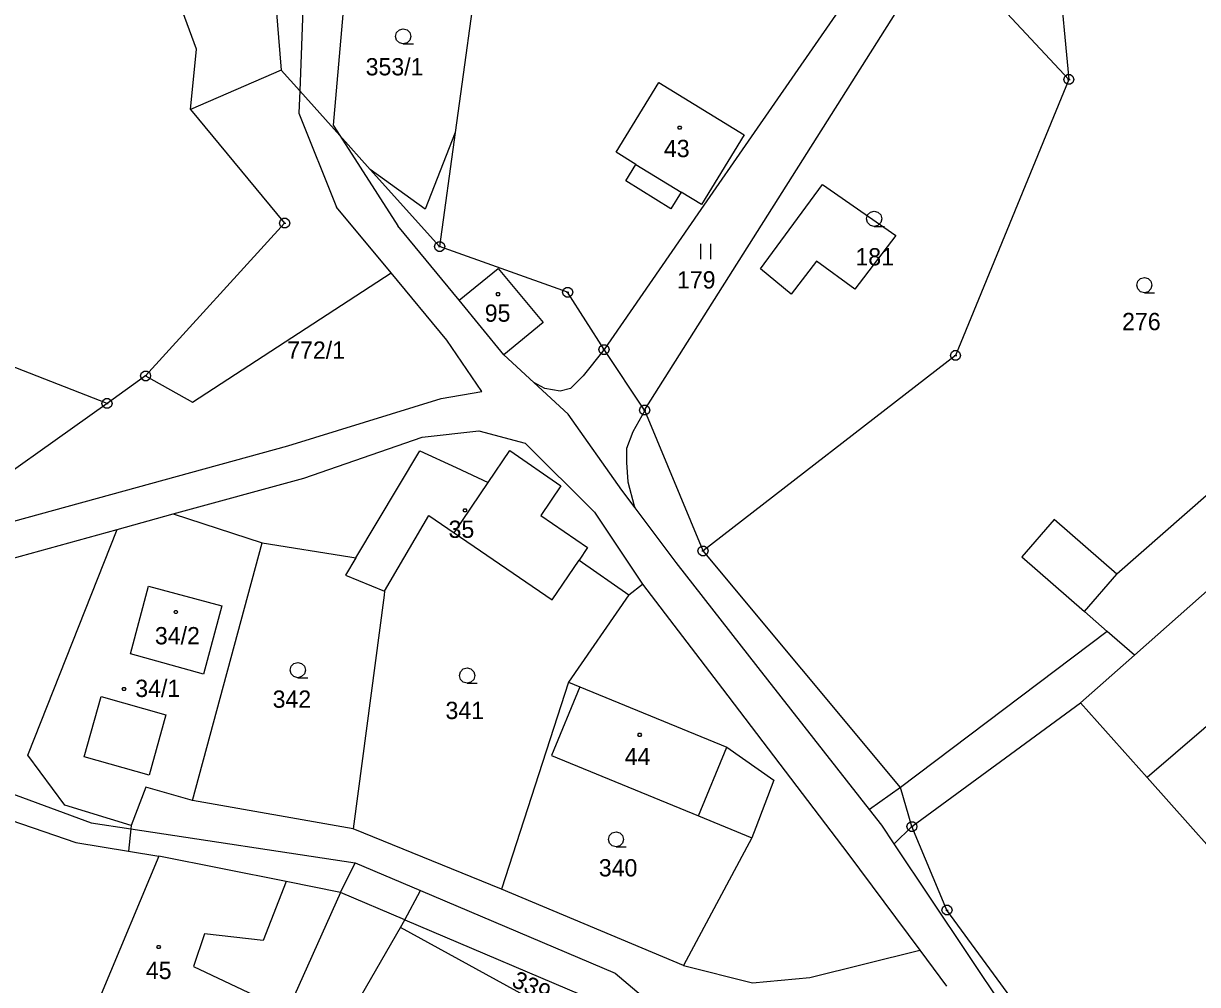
# Model space of a CAD drawing. Extents: x -694465 to -690527, y -983694 to -978978.
# Drawn here: x -693618.8 to -693503.4, y -981377.5 to -981283 of the extents above; entities that cross this region are included whole.
import ezdxf

# ---------------------------------------------------------------- set-up
doc = ezdxf.new("R2010")
doc.units = 0
for name, color, linetype in [('Vrstva 1', 7, 'Continuous'), ('Vrstva 18', 7, 'Continuous'), ('Vrstva 19', 7, 'Continuous'), ('Vrstva 24', 7, 'Continuous'), ('Vrstva 25', 7, 'Continuous')]:
    doc.layers.add(name, color=color, linetype=linetype)

msp = doc.modelspace()

# ---------------------------------------------------------------- linework, layer by layer
at = {"layer": 'Vrstva 1'}
for points in [[(-693518.05, -981266.92), (-693516.01, -981288.45)], [(-693594.85, -981270.62), (-693593.46, -981287.56)], [(-693531.56, -981271.43), (-693546.95, -981293.69)], [(-693601.8, -981285.49), (-693606.64, -981272.26)], [(-693590.99, -981271.78), (-693591.65, -981289.58)], [(-693586.58, -981272.65), (-693588.36, -981292.94)], [(-693557.73, -981320.98), (-693528.64, -981274.92)], [(-693516.01, -981288.45), (-693528.64, -981274.92)], [(-693573.91, -981275.82), (-693576.35, -981293.68)], [(-693602.38, -981291.42), (-693601.8, -981285.49)], [(-693593.46, -981287.56), (-693602.38, -981291.42)], [(-693591.65, -981289.58), (-693593.46, -981287.56)], [(-693558.58, -981296.82), (-693560.54, -981295.62), (-693556.34, -981288.75), (-693547.93, -981293.91)], [(-693516.01, -981288.45), (-693527.15, -981315.6)], [(-693591.65, -981289.58), (-693591.73, -981291.78)], [(-693587.69, -981293.98), (-693591.65, -981289.58)], [(-693602.38, -981291.42), (-693593.13, -981302.59)], [(-693591.73, -981291.78), (-693588.03, -981301.01)], [(-693588.36, -981292.94), (-693587.69, -981293.98)], [(-693584.71, -981297.3), (-693587.69, -981293.98)], [(-693587.69, -981293.98), (-693582.01, -981302.86)], [(-693576.35, -981293.68), (-693579.31, -981301.23)], [(-693576.35, -981293.68), (-693577.89, -981304.9)], [(-693547.93, -981293.91), (-693552.13, -981300.75), (-693554.14, -981299.53)], [(-693546.95, -981293.69), (-693552.48, -981301.67)], [(-693554.14, -981299.53), (-693555.14, -981301.17), (-693559.57, -981298.44), (-693558.58, -981296.82)], [(-693558.58, -981296.82), (-693554.14, -981299.53)], [(-693577.89, -981304.9), (-693584.71, -981297.3)], [(-693579.31, -981301.23), (-693584.71, -981297.3)], [(-693540.23, -981298.787), (-693533.033, -981303.821), (-693537.048, -981309.088), (-693540.812, -981306.329), (-693543.322, -981309.589), (-693546.333, -981307.082), (-693540.23, -981298.787)], [(-693582.661, -981307.477), (-693588.03, -981301.01)], [(-693593.13, -981302.59), (-693606.81, -981317.62)], [(-693552.48, -981301.67), (-693561.72, -981315.03)], [(-693575.97, -981310.18), (-693582.01, -981302.86)], [(-693565.3, -981309.39), (-693577.89, -981304.9)], [(-693575.97, -981310.18), (-693572.13, -981307.04)], [(-693572.13, -981307.04), (-693567.72, -981312.38), (-693571.58, -981315.54)], [(-693606.81, -981317.62), (-693602.192, -981320.191), (-693582.661, -981307.477)], [(-693577.17, -981314.09), (-693582.661, -981307.477)], [(-693610.6, -981320.32), (-693639.5, -981309.039)], [(-693561.72, -981315.03), (-693565.3, -981309.39)], [(-693571.58, -981315.54), (-693575.97, -981310.18)], [(-693573.75, -981319.16), (-693577.17, -981314.09)], [(-693561.72, -981315.03), (-693563.774, -981317.615), (-693565.028, -981318.869), (-693566.032, -981319.119), (-693567.538, -981318.869), (-693568.64, -981318.257)], [(-693557.73, -981320.98), (-693561.72, -981315.03)], [(-693486.54, -981315.4), (-693511.29, -981337.12)], [(-693568.64, -981318.257), (-693571.58, -981315.54)], [(-693527.15, -981315.6), (-693551.98, -981334.83)], [(-693606.81, -981317.62), (-693610.6, -981320.32)], [(-693565.25, -981321.39), (-693568.64, -981318.257)], [(-693592.81, -981324.5), (-693577.74, -981319.85)], [(-693577.74, -981319.85), (-693573.75, -981319.16)], [(-693610.6, -981320.32), (-693625.72, -981331.09)], [(-693557.71, -981321.027), (-693558.88, -981323.132), (-693559.508, -981324.762), (-693559.508, -981326.141), (-693559.382, -981328.022), (-693558.755, -981330.405), (-693558.663, -981330.589)], [(-693557.71, -981321.027), (-693557.73, -981320.98)], [(-693551.98, -981334.83), (-693557.71, -981321.027)], [(-693559.97, -981328.85), (-693565.25, -981321.39)], [(-693579.62, -981323.63), (-693574.03, -981323.01)], [(-693574.03, -981323.01), (-693569.46, -981324.23)], [(-693619.77, -981331.92), (-693592.81, -981324.5)], [(-693591.26, -981327.68), (-693579.62, -981323.63)], [(-693569.46, -981324.23), (-693562.66, -981331.03)], [(-693586.13, -981335.51), (-693579.85, -981324.99), (-693576.27, -981326.64), (-693573.1, -981328.1)], [(-693573.1, -981328.1), (-693570.97, -981324.97), (-693565.97, -981328.43), (-693567.95, -981331.34)], [(-693604.08, -981331.2), (-693591.26, -981327.68)], [(-693576.47, -981333.04), (-693573.1, -981328.1)], [(-693558.663, -981330.589), (-693559.97, -981328.85)], [(-693609.59, -981332.72), (-693604.08, -981331.2)], [(-693604.08, -981331.2), (-693595.35, -981334.04)], [(-693583.3, -981338.78), (-693578.95, -981331.35)], [(-693578.95, -981331.35), (-693576.47, -981333.04)], [(-693567.95, -981331.34), (-693563.34, -981334.48), (-693564.18, -981335.73)], [(-693562.66, -981331.03), (-693557.94, -981338.1)], [(-693554.61, -981335.98), (-693558.663, -981330.589)], [(-693620.05, -981335.6), (-693609.59, -981332.72)], [(-693618.4, -981354.93), (-693609.59, -981332.72)], [(-693517.45, -981331.74), (-693520.63, -981335.42)], [(-693511.29, -981337.12), (-693517.45, -981331.74)], [(-693576.47, -981333.04), (-693566.81, -981339.64)], [(-693602.19, -981359.39), (-693595.35, -981334.04)], [(-693595.35, -981334.04), (-693586.73, -981335.41), (-693586.13, -981335.51)], [(-693532.57, -981358.09), (-693551.98, -981334.83)], [(-693586.13, -981335.51), (-693587.15, -981337.23)], [(-693566.81, -981339.64), (-693564.18, -981335.73)], [(-693564.18, -981335.73), (-693559.29, -981339.15)], [(-693546.57, -981346.29), (-693554.61, -981335.98)], [(-693520.63, -981335.42), (-693514.48, -981340.78)], [(-693587.15, -981337.23), (-693583.3, -981338.78)], [(-693514.48, -981340.78), (-693511.29, -981337.12)], [(-693509.55, -981345.08), (-693499.804, -981336.469)], [(-693599.31, -981340.24), (-693601.11, -981346.96), (-693608.3, -981344.94), (-693606.52, -981338.3), (-693599.31, -981340.24)], [(-693559.29, -981339.15), (-693557.94, -981338.1)], [(-693557.94, -981338.1), (-693550.07, -981348.41)], [(-693583.35, -981339.18), (-693586.4, -981362.17)], [(-693583.3, -981338.78), (-693583.35, -981339.18)], [(-693559.29, -981339.15), (-693565.2, -981347.74)], [(-693514.48, -981340.78), (-693512.22, -981342.75)], [(-693512.22, -981342.75), (-693532.57, -981358.09)], [(-693509.55, -981345.08), (-693512.22, -981342.75)], [(-693491.815, -981342.943), (-693508.3, -981357.13)], [(-693514.86, -981349.77), (-693509.55, -981345.08)], [(-693535.623, -981360.259), (-693546.57, -981346.29)], [(-693565.2, -981347.74), (-693571.8, -981368.1)], [(-693565.2, -981347.74), (-693564.1, -981348.2)], [(-693564.1, -981348.2), (-693566.88, -981354.95)], [(-693564.1, -981348.2), (-693549.65, -981354.15)], [(-693550.07, -981348.41), (-693537.73, -981364.58)], [(-693612.85, -981355.1), (-693611.19, -981349.16)], [(-693611.19, -981349.16), (-693604.81, -981350.95)], [(-693531.44, -981361.95), (-693514.86, -981349.77)], [(-693514.86, -981349.77), (-693508.3, -981357.13)], [(-693604.81, -981350.95), (-693606.47, -981356.89)], [(-693552.43, -981360.9), (-693549.65, -981354.15)], [(-693549.65, -981354.15), (-693545.01, -981357.39), (-693546.8, -981362.04), (-693547.19, -981363.06)], [(-693614.74, -981359.85), (-693618.4, -981354.93)], [(-693606.47, -981356.89), (-693612.85, -981355.1)], [(-693566.88, -981354.95), (-693552.43, -981360.9)], [(-693626.94, -981356.15), (-693612.16, -981361.58)], [(-693631.73, -981357.32), (-693613.66, -981363.51)], [(-693606.8, -981358.06), (-693608.24, -981361.85)], [(-693602.19, -981359.39), (-693606.8, -981358.06)], [(-693532.57, -981358.09), (-693535.623, -981360.259)], [(-693531.44, -981361.95), (-693532.57, -981358.09)], [(-693508.3, -981357.13), (-693497.91, -981368.79)], [(-693608.24, -981361.85), (-693614.74, -981359.85)], [(-693586.4, -981362.17), (-693602.19, -981359.39)], [(-693534.4, -981361.82), (-693535.623, -981360.259)], [(-693612.16, -981361.58), (-693608.271, -981362.17)], [(-693552.43, -981360.9), (-693547.19, -981363.06)], [(-693608.271, -981362.17), (-693608.483, -981364.365)], [(-693608.24, -981361.85), (-693608.271, -981362.17)], [(-693608.271, -981362.17), (-693586.2, -981365.52)], [(-693571.8, -981368.1), (-693586.4, -981362.17)], [(-693533.19, -981363.629), (-693534.4, -981361.82)], [(-693531.44, -981361.95), (-693533.19, -981363.629)], [(-693527.99, -981370.15), (-693531.44, -981361.95)], [(-693613.66, -981363.51), (-693608.483, -981364.365)], [(-693547.19, -981363.06), (-693553.9, -981375.6)], [(-693518.63, -981385.4), (-693533.19, -981363.629)], [(-693605.49, -981364.86), (-693611.18, -981378.44)], [(-693608.483, -981364.365), (-693605.49, -981364.86)], [(-693592.98, -981367.36), (-693605.49, -981364.86)], [(-693537.73, -981364.58), (-693530.658, -981374.11)], [(-693587.65, -981368.42), (-693586.2, -981365.52)], [(-693586.2, -981365.52), (-693579.764, -981368.247)], [(-693592.98, -981367.36), (-693595.24, -981373.14)], [(-693587.65, -981368.42), (-693592.98, -981367.36)], [(-693587.65, -981368.42), (-693596.82, -981388.91)], [(-693581.3, -981371.12), (-693587.65, -981368.42)], [(-693581.3, -981371.12), (-693579.764, -981368.247)], [(-693579.764, -981368.247), (-693560.64, -981376.35)], [(-693553.9, -981375.6), (-693571.8, -981368.1)], [(-693520.64, -981380.22), (-693527.99, -981370.15)], [(-693586.52, -981380.16), (-693581.73, -981371.87)], [(-693581.73, -981371.87), (-693581.3, -981371.12)], [(-693567.57, -981379.63), (-693581.73, -981371.87)], [(-693581.3, -981371.12), (-693561.41, -981379.56)], [(-693601.01, -981372.49), (-693602.09, -981375.7)], [(-693595.24, -981373.14), (-693601.01, -981372.49)], [(-693553.9, -981375.6), (-693547.134, -981377.304), (-693541.491, -981376.791), (-693530.658, -981374.11)], [(-693530.658, -981374.11), (-693528.028, -981377.655)], [(-693602.09, -981375.7), (-693595.49, -981378.82)], [(-693560.64, -981376.35), (-693555.72, -981380.54)]]:
    msp.add_lwpolyline(points, dxfattribs=at)
at = {"layer": 'Vrstva 24'}
for points in [[(-693515.856, -981287.974), (-693515.606, -981288.156), (-693515.51, -981288.45), (-693515.606, -981288.744), (-693515.856, -981288.926), (-693516.164, -981288.926), (-693516.414, -981288.744), (-693516.51, -981288.45), (-693516.414, -981288.156), (-693516.164, -981287.974)], [(-693592.976, -981302.114), (-693592.726, -981302.296), (-693592.63, -981302.59), (-693592.726, -981302.884), (-693592.976, -981303.066), (-693593.284, -981303.066), (-693593.534, -981302.884), (-693593.63, -981302.59), (-693593.534, -981302.296), (-693593.284, -981302.114)], [(-693577.736, -981304.424), (-693577.486, -981304.606), (-693577.39, -981304.9), (-693577.486, -981305.194), (-693577.736, -981305.376), (-693578.044, -981305.376), (-693578.294, -981305.194), (-693578.39, -981304.9), (-693578.294, -981304.606), (-693578.044, -981304.424)], [(-693565.146, -981308.914), (-693564.896, -981309.096), (-693564.8, -981309.39), (-693564.896, -981309.684), (-693565.146, -981309.866), (-693565.454, -981309.866), (-693565.704, -981309.684), (-693565.8, -981309.39), (-693565.704, -981309.096), (-693565.454, -981308.914)], [(-693561.566, -981314.554), (-693561.316, -981314.736), (-693561.22, -981315.03), (-693561.316, -981315.324), (-693561.566, -981315.506), (-693561.874, -981315.506), (-693562.124, -981315.324), (-693562.22, -981315.03), (-693562.124, -981314.736), (-693561.874, -981314.554)], [(-693526.996, -981315.124), (-693526.746, -981315.306), (-693526.65, -981315.6), (-693526.746, -981315.894), (-693526.996, -981316.076), (-693527.304, -981316.076), (-693527.554, -981315.894), (-693527.65, -981315.6), (-693527.554, -981315.306), (-693527.304, -981315.124)], [(-693606.656, -981317.144), (-693606.406, -981317.326), (-693606.31, -981317.62), (-693606.406, -981317.914), (-693606.656, -981318.096), (-693606.964, -981318.096), (-693607.214, -981317.914), (-693607.31, -981317.62), (-693607.214, -981317.326), (-693606.964, -981317.144)], [(-693610.446, -981319.844), (-693610.196, -981320.026), (-693610.1, -981320.32), (-693610.196, -981320.614), (-693610.446, -981320.796), (-693610.754, -981320.796), (-693611.004, -981320.614), (-693611.1, -981320.32), (-693611.004, -981320.026), (-693610.754, -981319.844)], [(-693557.576, -981320.504), (-693557.326, -981320.686), (-693557.23, -981320.98), (-693557.326, -981321.274), (-693557.576, -981321.456), (-693557.884, -981321.456), (-693558.134, -981321.274), (-693558.23, -981320.98), (-693558.134, -981320.686), (-693557.884, -981320.504)], [(-693551.826, -981334.354), (-693551.576, -981334.536), (-693551.48, -981334.83), (-693551.576, -981335.124), (-693551.826, -981335.306), (-693552.134, -981335.306), (-693552.384, -981335.124), (-693552.48, -981334.83), (-693552.384, -981334.536), (-693552.134, -981334.354)], [(-693531.286, -981361.474), (-693531.036, -981361.656), (-693530.94, -981361.95), (-693531.036, -981362.244), (-693531.286, -981362.426), (-693531.594, -981362.426), (-693531.844, -981362.244), (-693531.94, -981361.95), (-693531.844, -981361.656), (-693531.594, -981361.474)], [(-693527.836, -981369.674), (-693527.586, -981369.856), (-693527.49, -981370.15), (-693527.586, -981370.444), (-693527.836, -981370.626), (-693528.144, -981370.626), (-693528.394, -981370.444), (-693528.49, -981370.15), (-693528.394, -981369.856), (-693528.144, -981369.674)]]:
    msp.add_lwpolyline(points, close=True, dxfattribs=at)
for points in [[(-693516.129, -981288.45), (-693515.89, -981288.45)], [(-693593.249, -981302.59), (-693593.01, -981302.59)], [(-693578.009, -981304.9), (-693577.77, -981304.9)], [(-693565.419, -981309.39), (-693565.18, -981309.39)], [(-693561.839, -981315.03), (-693561.6, -981315.03)], [(-693527.269, -981315.6), (-693527.03, -981315.6)], [(-693606.929, -981317.62), (-693606.69, -981317.62)], [(-693610.719, -981320.32), (-693610.48, -981320.32)], [(-693557.849, -981320.98), (-693557.61, -981320.98)], [(-693552.099, -981334.83), (-693551.86, -981334.83)], [(-693531.559, -981361.95), (-693531.32, -981361.95)], [(-693528.109, -981370.15), (-693527.87, -981370.15)]]:
    msp.add_lwpolyline(points, dxfattribs=at)
at = {"layer": 'Vrstva 25'}
for points in [[(-693581.47, -981284.97), (-693581.845, -981284.869), (-693582.119, -981284.595), (-693582.22, -981284.22), (-693582.119, -981283.845), (-693581.845, -981283.571), (-693581.47, -981283.47), (-693581.095, -981283.571), (-693580.821, -981283.845), (-693580.72, -981284.22), (-693580.821, -981284.595), (-693581.095, -981284.869), (-693581.47, -981284.97), (-693580.47, -981284.971)], [(-693535.15, -981302.91), (-693535.525, -981302.809), (-693535.799, -981302.535), (-693535.9, -981302.16), (-693535.799, -981301.785), (-693535.525, -981301.511), (-693535.15, -981301.41), (-693534.775, -981301.511), (-693534.501, -981301.785), (-693534.4, -981302.16), (-693534.501, -981302.535), (-693534.775, -981302.809), (-693535.15, -981302.91), (-693534.15, -981302.911)], [(-693552.23, -981304.62), (-693552.23, -981306.12)], [(-693551.23, -981306.12), (-693551.23, -981304.62)], [(-693508.58, -981309.44), (-693508.955, -981309.339), (-693509.229, -981309.065), (-693509.33, -981308.69), (-693509.229, -981308.315), (-693508.955, -981308.041), (-693508.58, -981307.94), (-693508.205, -981308.041), (-693507.931, -981308.315), (-693507.83, -981308.69), (-693507.931, -981309.065), (-693508.205, -981309.339), (-693508.58, -981309.44), (-693507.58, -981309.441)], [(-693591.84, -981347.3), (-693592.215, -981347.199), (-693592.489, -981346.925), (-693592.59, -981346.55), (-693592.489, -981346.175), (-693592.215, -981345.901), (-693591.84, -981345.8), (-693591.465, -981345.901), (-693591.191, -981346.175), (-693591.09, -981346.55), (-693591.191, -981346.925), (-693591.465, -981347.199), (-693591.84, -981347.3), (-693590.84, -981347.301)], [(-693575.19, -981347.84), (-693575.565, -981347.739), (-693575.839, -981347.465), (-693575.94, -981347.09), (-693575.839, -981346.715), (-693575.565, -981346.441), (-693575.19, -981346.34), (-693574.815, -981346.441), (-693574.541, -981346.715), (-693574.44, -981347.09), (-693574.541, -981347.465), (-693574.815, -981347.739), (-693575.19, -981347.84), (-693574.19, -981347.841)], [(-693560.54, -981363.95), (-693560.915, -981363.849), (-693561.189, -981363.575), (-693561.29, -981363.2), (-693561.189, -981362.825), (-693560.915, -981362.551), (-693560.54, -981362.45), (-693560.165, -981362.551), (-693559.891, -981362.825), (-693559.79, -981363.2), (-693559.891, -981363.575), (-693560.165, -981363.849), (-693560.54, -981363.95), (-693559.54, -981363.951)]]:
    msp.add_lwpolyline(points, dxfattribs=at)
for points in [[(-693554.203, -981293.048), (-693554.115, -981293.2), (-693554.203, -981293.352), (-693554.377, -981293.352), (-693554.465, -981293.2), (-693554.377, -981293.048)], [(-693572.053, -981309.428), (-693571.965, -981309.58), (-693572.053, -981309.732), (-693572.227, -981309.732), (-693572.315, -981309.58), (-693572.227, -981309.428)], [(-693575.303, -981330.688), (-693575.215, -981330.84), (-693575.303, -981330.992), (-693575.477, -981330.992), (-693575.565, -981330.84), (-693575.477, -981330.688)], [(-693603.743, -981340.698), (-693603.655, -981340.85), (-693603.743, -981341.002), (-693603.917, -981341.002), (-693604.005, -981340.85), (-693603.917, -981340.698)], [(-693608.843, -981348.268), (-693608.755, -981348.42), (-693608.843, -981348.572), (-693609.017, -981348.572), (-693609.105, -981348.42), (-693609.017, -981348.268)], [(-693558.133, -981352.768), (-693558.045, -981352.92), (-693558.133, -981353.072), (-693558.307, -981353.072), (-693558.395, -981352.92), (-693558.307, -981352.768)], [(-693605.443, -981373.628), (-693605.355, -981373.78), (-693605.443, -981373.932), (-693605.617, -981373.932), (-693605.705, -981373.78), (-693605.617, -981373.628)]]:
    msp.add_lwpolyline(points, close=True, dxfattribs=at)

# ---------------------------------------------------------------- texts
at = {"layer": 'Vrstva 18'}
for s, p in [('353/1', (-693585.166, -981288.06)), ('181', (-693536.995, -981306.75)), ('179', (-693554.546, -981309.02)), ('276', (-693510.768, -981313.12)), ('772/1', (-693592.883, -981315.93)), ('342', (-693594.315, -981350.26)), ('341', (-693577.313, -981351.37)), ('340', (-693562.233, -981366.85))]:
    msp.add_text(s, height=1.7, dxfattribs=at).set_placement(p)
msp.add_text('339', height=1.7, rotation=335.12301, dxfattribs=at).set_placement((-693570.915, -981377.61))
at = {"layer": 'Vrstva 19'}
for s, p in [('43', (-693555.832, -981296.1)), ('95', (-693573.452, -981312.29)), ('35', (-693577.009, -981333.55)), ('34/2', (-693605.893, -981344.02)), ('34/1', (-693607.823, -981349.2)), ('44', (-693559.685, -981355.9)), ('45', (-693606.782, -981376.94))]:
    msp.add_text(s, height=1.7, dxfattribs=at).set_placement(p)

doc.saveas('drawing.dxf')
